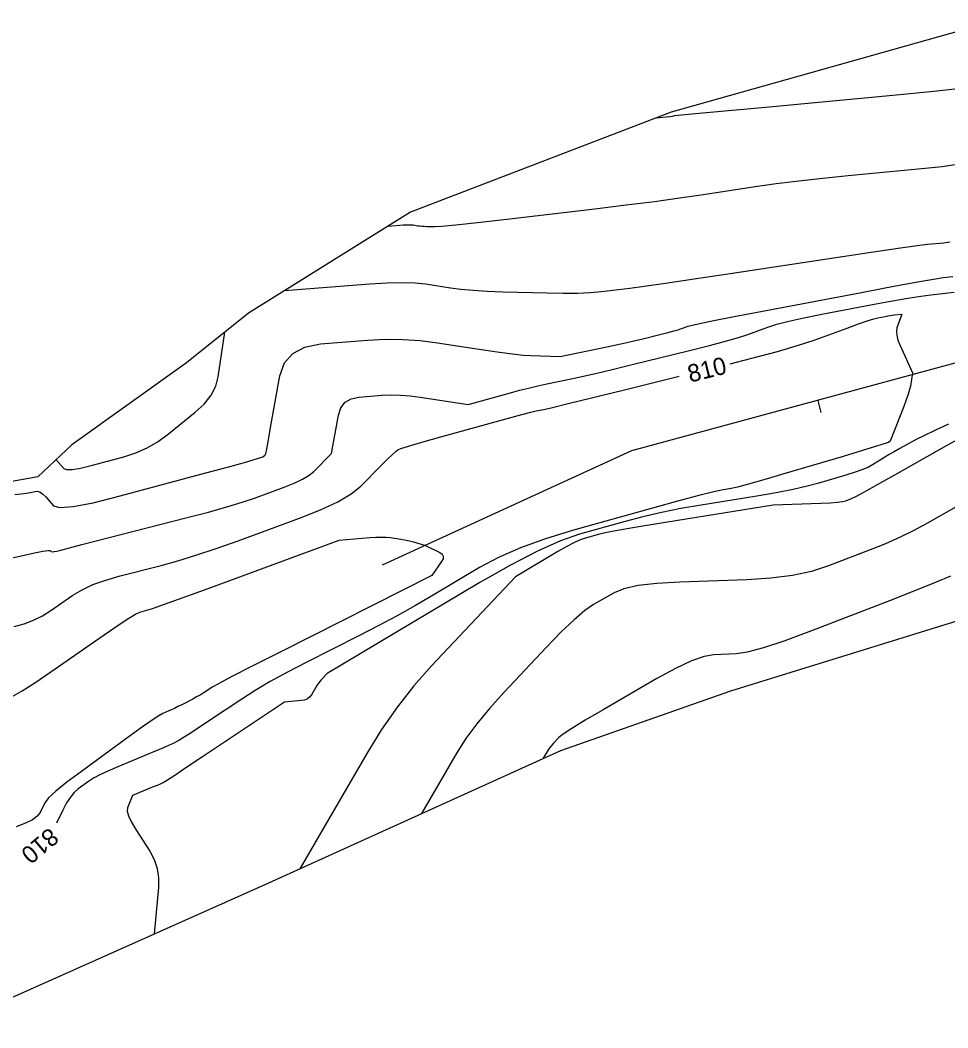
# Model space of a CAD drawing. Extents: x 1715724 to 1716561, y 394063 to 395906.
# Drawn here: x 1715858.3 to 1715932.8, y 394944.8 to 395025.7 of the extents above; entities that cross this region are included whole.
import ezdxf

# ---------------------------------------------------------------- set-up
doc = ezdxf.new("R2010")
doc.units = 0
for name, color, linetype in [('DT_X_Contour_Major', 7, 'Continuous'), ('DT_X_Contour_Minor', 7, 'Continuous'), ('DT_X_TIN_Hull', 7, 'Continuous'), ('GE_P_CL_10', 7, 'Continuous')]:
    doc.layers.add(name, color=color, linetype=linetype)

msp = doc.modelspace()

# ---------------------------------------------------------------- linework, layer by layer
at = {"layer": 'DT_X_Contour_Major'}
for points in [[(1715909.398, 395017.822), (1715910.496, 395017.952), (1715910.691, 395017.979), (1715910.886, 395018.008), (1715911.415, 395018.061), (1715912.855, 395018.198), (1715918.471, 395018.723), (1715928.388, 395019.646), (1715931.678, 395019.966), (1715934.11, 395020.233)], [(1715915.323, 394998.086), (1715916.976, 394998.502), (1715919.138, 394999.078), (1715920.835, 394999.571), (1715922.067, 394999.98), (1715924.735, 395000.958), (1715925.639, 395001.284), (1715926.348, 395001.529), (1715926.863, 395001.693), (1715927.184, 395001.776), (1715927.78, 395001.888), (1715927.993, 395001.927), (1715928.183, 395001.96), (1715928.352, 395001.985), (1715928.498, 395002.004), (1715929.129, 395002.076), (1715928.731, 395000.967), (1715928.683, 395000.7), (1715928.709, 395000.375), (1715928.81, 394999.992), (1715928.985, 394999.551), (1715929.974, 394997.356), (1715929.805, 394996.296), (1715929.744, 394996.022), (1715929.635, 394995.656), (1715929.477, 394995.198), (1715929.27, 394994.647), (1715928.193, 394991.859), (1715928.039, 394991.76), (1715927.787, 394991.675), (1715927.097, 394991.462), (1715925.969, 394991.122), (1715924.403, 394990.654), (1715919.643, 394989.237), (1715918.039, 394988.765), (1715916.798, 394988.412), (1715915.918, 394988.179), (1715915.401, 394988.065), (1715914.505, 394987.919), (1715913.914, 394987.789), (1715912.815, 394987.506), (1715911.206, 394987.072), (1715909.089, 394986.486), (1715902.763, 394984.72), (1715900.513, 394984.037), (1715898.504, 394983.31), (1715896.738, 394982.541), (1715895.214, 394981.729), (1715891.474, 394979.506), (1715890.049, 394978.676), (1715888.578, 394977.855), (1715887.062, 394977.042), (1715885.501, 394976.237), (1715881.278, 394974.103), (1715879.767, 394973.319), (1715878.401, 394972.567), (1715877.181, 394971.849), (1715876.106, 394971.163), (1715873.434, 394969.378), (1715872.534, 394968.78), (1715871.836, 394968.325), (1715871.342, 394968.012), (1715871.051, 394967.843), (1715870.546, 394967.582), (1715870.272, 394967.452), (1715869.831, 394967.257), (1715869.223, 394966.998), (1715868.446, 394966.674), (1715866.152, 394965.725), (1715865.36, 394965.385), (1715864.704, 394965.077), (1715864.186, 394964.8), (1715863.804, 394964.555), (1715862.968, 394963.945), (1715862.656, 394963.668), (1715862.347, 394963.294), (1715862.04, 394962.824), (1715861.737, 394962.257), (1715861.22, 394961.203)], [(1715857.829, 394977.001), (1715858.622, 394977.212), (1715859.377, 394977.495), (1715860.095, 394977.849), (1715860.776, 394978.275), (1715862.543, 394979.504), (1715863.277, 394979.947), (1715864.155, 394980.353), (1715865.177, 394980.723), (1715866.343, 394981.056), (1715869.645, 394981.895), (1715870.96, 394982.255), (1715872.427, 394982.707), (1715874.047, 394983.249), (1715875.819, 394983.882), (1715880.749, 394985.692), (1715882.442, 394986.362), (1715883.825, 394987.014), (1715884.897, 394987.647), (1715885.658, 394988.262), (1715887.273, 394989.879), (1715887.813, 394990.414), (1715888.224, 394990.809), (1715888.504, 394991.061), (1715888.655, 394991.173), (1715888.883, 394991.282), (1715889.149, 394991.371), (1715889.774, 394991.555), (1715890.76, 394991.836), (1715892.106, 394992.212), (1715896.174, 394993.344), (1715897.543, 394993.723), (1715898.597, 394994.009), (1715899.337, 394994.203), (1715899.762, 394994.304), (1715900.478, 394994.452), (1715901.07, 394994.588), (1715902.309, 394994.886), (1715904.196, 394995.346), (1715906.73, 394995.968), (1715911.246, 394997.078)]]:
    msp.add_lwpolyline(points, dxfattribs=at)
at = {"layer": 'DT_X_Contour_Minor'}
for points in [[(1715887.861, 395009.132), (1715889.081, 395009.229), (1715889.326, 395009.245), (1715889.541, 395009.25), (1715889.723, 395009.245), (1715889.875, 395009.229), (1715890.236, 395009.173), (1715890.385, 395009.154), (1715890.559, 395009.138), (1715890.758, 395009.126), (1715890.984, 395009.117), (1715891.618, 395009.099), (1715892.158, 395009.132), (1715893.3, 395009.245), (1715895.046, 395009.436), (1715897.394, 395009.708), (1715904.459, 395010.537), (1715906.981, 395010.84), (1715909.247, 395011.127), (1715911.258, 395011.399), (1715913.013, 395011.654), (1715917.352, 395012.314), (1715919.04, 395012.556), (1715920.847, 395012.784), (1715922.775, 395012.999), (1715924.822, 395013.202), (1715930.443, 395013.725), (1715932.365, 395013.933), (1715933.915, 395014.165)], [(1715879.548, 395003.958), (1715886.395, 395004.504), (1715887.774, 395004.591), (1715888.977, 395004.62), (1715890.002, 395004.59), (1715890.852, 395004.501), (1715892.881, 395004.187), (1715893.714, 395004.079), (1715894.69, 395003.991), (1715895.811, 395003.922), (1715897.075, 395003.874), (1715900.638, 395003.773), (1715901.913, 395003.752), (1715903.066, 395003.766), (1715904.098, 395003.814), (1715905.008, 395003.896), (1715907.273, 395004.162), (1715908.414, 395004.31), (1715910.138, 395004.553), (1715912.445, 395004.893), (1715915.335, 395005.329), (1715923.819, 395006.62), (1715926.664, 395007.05), (1715928.839, 395007.37), (1715930.342, 395007.58), (1715931.174, 395007.681), (1715932.497, 395007.804), (1715932.983, 395007.869)], [(1715857.874, 394987.6), (1715858.601, 394987.67), (1715858.976, 394987.722), (1715859.506, 394987.839), (1715859.709, 394987.844), (1715859.921, 394987.772), (1715860.142, 394987.623), (1715860.372, 394987.397), (1715860.996, 394986.691), (1715861.505, 394986.542), (1715862.564, 394986.622), (1715864.174, 394986.932), (1715866.333, 394987.472), (1715872.825, 394989.219), (1715874.962, 394989.797), (1715876.504, 394990.223), (1715877.452, 394990.497), (1715877.804, 394990.617), (1715877.951, 394990.735), (1715878.001, 394990.79), (1715878.043, 394990.865), (1715878.075, 394990.96), (1715878.098, 394991.075), (1715878.148, 394991.41), (1715878.191, 394991.665), (1715878.42, 394992.959), (1715879.17, 394997.113), (1715879.532, 394998.149), (1715880.196, 394998.922), (1715881.163, 394999.431), (1715882.431, 394999.676), (1715886.217, 394999.977), (1715887.632, 395000.05), (1715889.039, 395000.04), (1715890.438, 394999.948), (1715891.829, 394999.774), (1715895.526, 394999.2), (1715896.802, 394999.01), (1715897.859, 394998.871), (1715898.695, 394998.781), (1715899.312, 394998.741), (1715901.678, 394998.674), (1715905.415, 394999.446), (1715906.19, 394999.609), (1715906.914, 394999.768), (1715907.588, 394999.921), (1715908.21, 395000.071), (1715909.802, 395000.462), (1715910.351, 395000.6), (1715910.802, 395000.72), (1715911.157, 395000.823), (1715911.414, 395000.909), (1715911.972, 395001.113), (1715912.52, 395001.249), (1715913.746, 395001.504), (1715915.651, 395001.878), (1715918.234, 395002.372), (1715926.026, 395003.845), (1715928.618, 395004.333), (1715930.552, 395004.691), (1715931.827, 395004.918), (1715932.444, 395005.016), (1715933.209, 395005.103)], [(1715855.668, 394982.071), (1715858.519, 394982.699), (1715859.458, 394982.9), (1715860.138, 394983.034), (1715860.558, 394983.1), (1715860.719, 394983.099), (1715860.802, 394983.005), (1715860.874, 394982.986), (1715861.028, 394983.001), (1715861.265, 394983.048), (1715861.584, 394983.129), (1715863.265, 394983.581), (1715871.73, 394985.733), (1715873.428, 394986.177), (1715874.896, 394986.587), (1715876.132, 394986.964), (1715877.137, 394987.308), (1715879.508, 394988.179), (1715880.325, 394988.503), (1715880.995, 394988.821), (1715881.519, 394989.135), (1715881.898, 394989.443), (1715883.323, 394990.87), (1715883.883, 394993.97), (1715884.076, 394994.558), (1715884.413, 394994.994), (1715884.894, 394995.278), (1715885.521, 394995.41), (1715887.384, 394995.559), (1715888.099, 394995.591), (1715888.846, 394995.578), (1715889.625, 394995.519), (1715890.436, 394995.413), (1715894.296, 394994.815), (1715897.687, 394995.758), (1715898.415, 394995.954), (1715899.143, 394996.137), (1715899.873, 394996.307), (1715900.603, 394996.465), (1715902.553, 394996.868), (1715903.408, 394997.053), (1715904.513, 394997.307), (1715905.867, 394997.629), (1715907.47, 394998.019), (1715912.076, 394999.152), (1715913.663, 394999.551), (1715914.97, 394999.899), (1715915.996, 395000.197), (1715916.741, 395000.444), (1715918.354, 395001.035), (1715919.079, 395001.266), (1715920.047, 395001.517), (1715921.257, 395001.786), (1715922.709, 395002.074), (1715926.903, 395002.867), (1715928.367, 395003.137), (1715929.613, 395003.353), (1715930.642, 395003.515), (1715931.452, 395003.622), (1715933.323, 395003.836)], [(1715861.193, 394990.375), (1715861.803, 394989.685), (1715862.039, 394989.589), (1715862.489, 394989.595), (1715863.15, 394989.705), (1715864.024, 394989.917), (1715866.637, 394990.62), (1715867.596, 394990.932), (1715868.511, 394991.341), (1715869.384, 394991.847), (1715870.214, 394992.451), (1715872.371, 394994.189), (1715873.093, 394994.855), (1715873.641, 394995.552), (1715874.016, 394996.278), (1715874.217, 394997.034), (1715874.752, 395000.631)], [(1715932.864, 394993.248), (1715931.759, 394992.731), (1715930.898, 394992.313), (1715930.281, 394991.995), (1715928.962, 394991.278), (1715928.497, 394991.022), (1715928.091, 394990.792), (1715927.746, 394990.587), (1715927.459, 394990.407), (1715926.776, 394989.963), (1715926.449, 394989.787), (1715925.983, 394989.592), (1715925.376, 394989.377), (1715924.629, 394989.143), (1715922.449, 394988.494), (1715921.525, 394988.247), (1715920.386, 394987.993), (1715919.034, 394987.732), (1715917.467, 394987.464), (1715913.005, 394986.74), (1715911.368, 394986.454), (1715909.806, 394986.14), (1715908.318, 394985.798), (1715906.904, 394985.428), (1715903.234, 394984.403), (1715901.701, 394983.872), (1715899.855, 394983.046), (1715897.696, 394981.925), (1715895.224, 394980.511), (1715882.959, 394973.22), (1715882.475, 394972.706), (1715882.369, 394972.584), (1715882.259, 394972.437), (1715882.144, 394972.265), (1715882.025, 394972.068), (1715881.701, 394971.51), (1715881.558, 394971.324), (1715881.374, 394971.184), (1715881.149, 394971.089), (1715880.882, 394971.041), (1715879.54, 394970.921), (1715872.882, 394966.473), (1715871.628, 394965.636), (1715870.718, 394965.031), (1715870.153, 394964.658), (1715869.932, 394964.517), (1715869.803, 394964.45), (1715869.716, 394964.409), (1715869.552, 394964.339), (1715869.311, 394964.237), (1715868.993, 394964.105), (1715867.331, 394963.418), (1715866.933, 394962.427), (1715866.911, 394962.159), (1715867.014, 394961.781), (1715867.244, 394961.292), (1715867.601, 394960.691), (1715868.719, 394958.943), (1715869.077, 394958.27), (1715869.311, 394957.56), (1715869.423, 394956.815), (1715869.412, 394956.033), (1715869.072, 394952.304)], [(1715934.201, 394992.335), (1715932.735, 394991.529), (1715928.541, 394989.148), (1715927.143, 394988.358), (1715926.097, 394987.776), (1715925.401, 394987.4), (1715925.057, 394987.232), (1715924.605, 394987.058), (1715924.354, 394986.997), (1715923.94, 394986.946), (1715923.362, 394986.904), (1715922.62, 394986.871), (1715918.776, 394986.741), (1715909.471, 394985.23), (1715907.678, 394984.934), (1715906.289, 394984.692), (1715905.303, 394984.504), (1715904.72, 394984.37), (1715903.704, 394984.087), (1715903.279, 394983.939), (1715902.768, 394983.711), (1715902.17, 394983.4), (1715901.486, 394983.008), (1715898.089, 394980.99), (1715891.346, 394973.825), (1715889.938, 394972.234), (1715888.603, 394970.531), (1715887.341, 394968.717), (1715886.153, 394966.79), (1715880.778, 394957.54)], [(1715933.851, 394986.807), (1715931.138, 394985.267), (1715930.091, 394984.701), (1715928.983, 394984.158), (1715927.815, 394983.638), (1715926.587, 394983.142), (1715923.232, 394981.849), (1715921.879, 394981.416), (1715920.335, 394981.088), (1715918.6, 394980.863), (1715916.674, 394980.742), (1715911.285, 394980.559), (1715909.44, 394980.455), (1715907.945, 394980.277), (1715906.802, 394980.028), (1715906.009, 394979.706), (1715904.362, 394978.751), (1715903.662, 394978.269), (1715902.799, 394977.538), (1715901.772, 394976.559), (1715900.582, 394975.332), (1715897.189, 394971.727), (1715895.999, 394970.412), (1715894.974, 394969.17), (1715894.113, 394968.003), (1715893.416, 394966.908), (1715890.548, 394961.973)], [(1715857.725, 394971.395), (1715858.46, 394971.814), (1715859.479, 394972.468), (1715860.781, 394973.356), (1715864.633, 394976.037), (1715865.922, 394976.923), (1715866.902, 394977.571), (1715867.571, 394977.981), (1715867.931, 394978.152), (1715868.476, 394978.291), (1715868.937, 394978.44), (1715869.911, 394978.783), (1715871.398, 394979.32), (1715873.398, 394980.052), (1715883.929, 394983.918), (1715886.384, 394984.13), (1715886.883, 394984.164), (1715887.328, 394984.174), (1715887.718, 394984.161), (1715888.055, 394984.125), (1715888.881, 394983.997), (1715889.178, 394983.947), (1715889.447, 394983.895), (1715889.691, 394983.84), (1715889.907, 394983.782), (1715890.856, 394983.505), (1715892.006, 394982.932), (1715892.2, 394982.795), (1715892.291, 394982.628), (1715892.277, 394982.432), (1715892.159, 394982.207), (1715891.364, 394981.088), (1715879.296, 394974.988), (1715877.009, 394973.828), (1715875.319, 394972.963), (1715874.229, 394972.392), (1715873.736, 394972.115), (1715873.219, 394971.77), (1715873.008, 394971.635), (1715872.763, 394971.49), (1715872.484, 394971.335), (1715872.171, 394971.169), (1715871.289, 394970.714), (1715870.977, 394970.555), (1715870.701, 394970.42), (1715870.463, 394970.308), (1715870.26, 394970.22), (1715869.771, 394970.017), (1715869.445, 394969.83), (1715868.834, 394969.421), (1715867.938, 394968.789), (1715866.758, 394967.935), (1715863.232, 394965.361), (1715862.057, 394964.48), (1715861.177, 394963.766), (1715860.591, 394963.221), (1715860.299, 394962.843), (1715859.915, 394962.059), (1715859.686, 394961.767), (1715859.29, 394961.477), (1715858.725, 394961.191), (1715857.992, 394960.907)], [(1715933.038, 394981.043), (1715931.869, 394980.54), (1715930.229, 394979.876), (1715928.118, 394979.052), (1715921.859, 394976.64), (1715919.721, 394975.846), (1715918.003, 394975.273), (1715916.703, 394974.919), (1715915.822, 394974.786), (1715914.032, 394974.725), (1715913.243, 394974.588), (1715912.216, 394974.222), (1715910.953, 394973.627), (1715909.453, 394972.803), (1715905.136, 394970.301), (1715903.7, 394969.459), (1715902.629, 394968.809), (1715901.922, 394968.351), (1715901.579, 394968.085), (1715901.153, 394967.632), (1715901.004, 394967.466), (1715900.875, 394967.31), (1715900.767, 394967.164), (1715900.679, 394967.026), (1715900.319, 394966.406)]]:
    msp.add_lwpolyline(points, dxfattribs=at)
at = {"layer": 'DT_X_TIN_Hull'}
for points in [[(1715936.829, 395025.676), (1715910.582, 395018.276), (1715889.663, 395010.254), (1715876.644, 395002.15), (1715871.667, 394998.153), (1715862.468, 394991.564), (1715859.732, 394989.013), (1715839.778, 394985.423)], [(1715852.156, 394944.766), (1715878.269, 394956.402), (1715901.723, 394967.043), (1715915.398, 394971.824), (1715935.897, 394978.157)]]:
    msp.add_lwpolyline(points, dxfattribs=at)
at = {"layer": 'GE_P_CL_10'}
for p, q in [((1715956.915, 395004.529), (1715907.412, 394991.084)), ((1715922.365, 394995.145), (1715922.627, 394994.18)), ((1715907.412, 394991.084), (1715887.376, 394981.912))]:
    msp.add_line(p, q, dxfattribs=at)

# ---------------------------------------------------------------- texts
at = {"layer": 'DT_X_Contour_Major'}
for rotation, p in [(13.88476, (1715912.116, 394996.569)), (219.91318, (1715860.65, 394960.912))]:
    msp.add_text('810', height=1.4, rotation=rotation, dxfattribs=at).set_placement(p)

doc.saveas('drawing.dxf')
